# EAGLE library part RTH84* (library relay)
Power PCB Relay 105°C sensitive SCHRACK 1 pole 10 A, high-temperature version Source: http://www.schrack.com/.. 5828.pdf
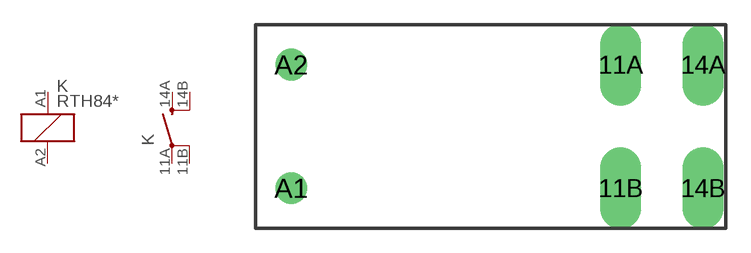
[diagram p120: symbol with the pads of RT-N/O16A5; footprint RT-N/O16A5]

Designator prefix K; gates 1=K 2=S-X2

## RTH84012 (OC_FARNELL: unknown; OC_NEWARK: unknown), RTH84024 (OC_FARNELL: unknown; OC_NEWARK: unknown)  [RT-N/O16A5]
11A  2:PA  pas
11B  2:PB  pas
14A  2:SA  pas
14B  2:SB  pas
A1  1:1  pas
A2  1:2  pas

## Footprint RT-N/O16A5 (pad centres in mm)
Power PCB Relay 1 pole 12 / 16 A, DC- or AC-coil SCHRACK 16 A, pinning 5mm Source: http://www.schrack.com/.. 5819.pdf
drill 1.3 pad 2.5 long: 11A 7.56,3.78; 11B 7.56,-3.78; 14A 12.6,3.78; 14B 12.6,-3.78
drill 1.3 round: A1 -12.6,-3.78; A2 -12.6,3.78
